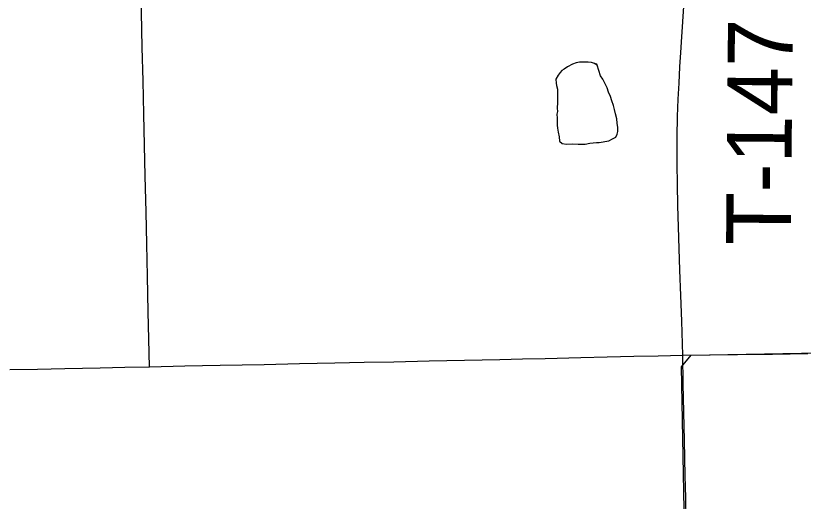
# Model space of a CAD drawing. Extents: x -11.4 to 84.1, y 11.1 to 59.
# Drawn here: x 31.454 to 32.145, y 41.894 to 42.32 of the extents above; entities that cross this region are included whole.
import ezdxf

# ---------------------------------------------------------------- set-up
doc = ezdxf.new("R2010")
doc.units = 0
for name, color, linetype in [('GM_X_County_Road', 7, 'Continuous'), ('GM_X_Minor_Lake', 7, 'Continuous'), ('GM_X_Rail_Line', 7, 'Continuous'), ('GM_X_Township_Road', 7, 'Continuous'), ('GM_X_Township_Road_Text', 7, 'Continuous')]:
    doc.layers.add(name, color=color, linetype=linetype)

msp = doc.modelspace()

# ---------------------------------------------------------------- linework, layer by layer
at = {"layer": 'GM_X_County_Road'}
for points in [[(32.03893, 42.02238), (32.06291, 42.02261), (32.08688, 42.02284), (32.11774, 42.02325), (32.14859, 42.02367)], [(31.44876, 42.00964), (31.47288, 42.01015), (31.497, 42.01066), (31.52806, 42.01129), (31.54959, 42.01173), (31.57112, 42.01217), (31.60218, 42.01283), (31.63324, 42.01348), (31.65249, 42.01388), (31.67174, 42.01429), (31.7028, 42.01492), (31.73387, 42.01555), (31.75965, 42.01607), (31.78544, 42.01659), (31.8165, 42.01726), (31.84756, 42.01793), (31.87863, 42.0186), (31.89851, 42.01903), (31.91839, 42.01946), (31.94946, 42.02021), (31.97275, 42.02078), (31.99605, 42.02134), (32.01749, 42.02186), (32.03893, 42.02238)], [(32.04757, 41.49618), (32.04818, 41.50923), (32.04827, 41.52236), (32.04835, 41.53715), (32.04814, 41.56822), (32.04802, 41.58528), (32.0479, 41.60235), (32.04777, 41.63342), (32.0477, 41.64896), (32.04763, 41.66451), (32.04709, 41.69149), (32.04655, 41.71847), (32.0457, 41.74607), (32.04485, 41.77367), (32.044, 41.80472), (32.04342, 41.82576), (32.04284, 41.8468), (32.04208, 41.87786), (32.04161, 41.89712), (32.04114, 41.91638), (32.04044, 41.94744), (32.03988, 41.97237), (32.03932, 41.99731), (32.03893, 42.02238)]]:
    msp.add_lwpolyline(points, dxfattribs=at)
at = {"layer": 'GM_X_Minor_Lake'}
for points in [[(31.964, 42.27679), (31.9617, 42.27827), (31.96361, 42.27755), (31.9617, 42.27827), (31.95903, 42.27899), (31.95598, 42.27932), (31.9537, 42.27928), (31.95143, 42.27925), (31.94839, 42.2792), (31.94536, 42.27877), (31.94234, 42.27758), (31.93782, 42.27522), (31.93482, 42.27327), (31.93293, 42.2721), (31.93145, 42.27017), (31.92959, 42.26786), (31.92775, 42.26441), (31.92781, 42.26099), (31.92822, 42.25872), (31.92904, 42.25569), (31.92914, 42.2496), (31.92923, 42.24391), (31.92894, 42.23896), (31.92899, 42.23592), (31.92865, 42.23363), (31.9287, 42.23021), (31.92876, 42.22717), (31.92881, 42.22413), (31.92923, 42.22147), (31.92967, 42.21806), (31.9305, 42.21389)], [(31.964, 42.27679), (31.9617, 42.27827), (31.96361, 42.27755), (31.9617, 42.27827), (31.95903, 42.27899), (31.95598, 42.27932), (31.9537, 42.27928), (31.95143, 42.27925), (31.94839, 42.2792), (31.94536, 42.27877), (31.94234, 42.27758), (31.93782, 42.27522), (31.93482, 42.27327), (31.93293, 42.2721), (31.93145, 42.27017), (31.92959, 42.26786), (31.92775, 42.26441), (31.92781, 42.26099), (31.92822, 42.25872), (31.92904, 42.25569), (31.92914, 42.2496), (31.92923, 42.24391), (31.92894, 42.23896), (31.92899, 42.23592), (31.92865, 42.23363), (31.9287, 42.23021), (31.92876, 42.22717), (31.92881, 42.22413), (31.92923, 42.22147), (31.92967, 42.21806), (31.9305, 42.21389), (31.93094, 42.21009), (31.93326, 42.20785), (31.93706, 42.20753), (31.942, 42.20761), (31.94732, 42.20732), (31.95112, 42.20738), (31.9534, 42.20742), (31.95756, 42.20825), (31.96325, 42.20872), (31.96553, 42.20876), (31.97424, 42.21042), (31.97725, 42.21199), (31.98026, 42.21356), (31.98136, 42.21624), (31.98208, 42.21854), (31.98202, 42.22196), (31.98158, 42.22575), (31.98113, 42.22955), (31.97991, 42.23409), (31.97909, 42.23788), (31.97827, 42.24129), (31.97668, 42.24544), (31.97548, 42.24922), (31.9739, 42.253), (31.9727, 42.25678), (31.97152, 42.25905), (31.97073, 42.26093), (31.96877, 42.26432), (31.96682, 42.26733), (31.964, 42.27679)], [(31.9305, 42.21389), (31.93094, 42.21009), (31.93326, 42.20785), (31.93706, 42.20753), (31.942, 42.20761), (31.94732, 42.20732), (31.95112, 42.20738), (31.9534, 42.20742), (31.95756, 42.20825), (31.96325, 42.20872), (31.96553, 42.20876), (31.97424, 42.21042), (31.97725, 42.21199), (31.98026, 42.21356), (31.98136, 42.21624), (31.98208, 42.21854), (31.98202, 42.22196), (31.98158, 42.22575), (31.98113, 42.22955), (31.97991, 42.23409), (31.97909, 42.23788), (31.97827, 42.24129), (31.97668, 42.24544), (31.97548, 42.24922), (31.9739, 42.253), (31.9727, 42.25678), (31.97152, 42.25905), (31.97073, 42.26093), (31.96877, 42.26432), (31.96682, 42.26733), (31.964, 42.27679)]]:
    msp.add_lwpolyline(points, dxfattribs=at)
at = {"layer": 'GM_X_Rail_Line'}
msp.add_lwpolyline([(26.71732, 41.55544), (27.05302, 41.37164), (27.55347, 41.38096), (28.60002, 41.4108), (30.15821, 41.45182), (31.07244, 41.47046), (32.03512, 41.49936), (32.04724, 41.51148), (32.03792, 42.0121), (32.04631, 42.02236), (33.0454, 42.04058)], dxfattribs=at)
at = {"layer": 'GM_X_Township_Road'}
for points in [[(31.57112, 42.01217), (31.57055, 42.03629), (31.56999, 42.06042), (31.56935, 42.09148), (31.56876, 42.11981), (31.56818, 42.14813), (31.56752, 42.17919), (31.56695, 42.20641), (31.56637, 42.23362), (31.56559, 42.26288), (31.56482, 42.29214), (31.5642, 42.32321), (31.5638, 42.34327), (31.5634, 42.36333), (31.56266, 42.3944), (31.56205, 42.41989), (31.56143, 42.44537), (31.56106, 42.46334), (31.56112, 42.469), (31.56162, 42.47419), (31.56273, 42.47924), (31.5647, 42.48516)], [(32.03893, 42.02238), (32.03806, 42.05224), (32.03728, 42.07463), (32.03651, 42.09702), (32.03563, 42.12531), (32.03474, 42.1536), (32.0344, 42.17189), (32.03406, 42.19018), (32.03396, 42.2137), (32.03445, 42.23165), (32.03493, 42.24696), (32.03571, 42.26091), (32.0365, 42.27525), (32.03727, 42.28784), (32.03815, 42.30159), (32.03991, 42.32813)]]:
    msp.add_lwpolyline(points, dxfattribs=at)

# ---------------------------------------------------------------- texts
at = {"layer": 'GM_X_Township_Road_Text'}
msp.add_text('T-147', height=0.056818, rotation=89.5007, dxfattribs=at).set_placement((32.13379, 42.11849))

doc.saveas('drawing.dxf')
